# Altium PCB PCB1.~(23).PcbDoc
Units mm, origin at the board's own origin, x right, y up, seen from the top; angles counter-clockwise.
Board outline 32.13 x 39.5 mm, 2 copper layers (Top Layer, Bottom Layer); 17 components, 6 nets, 40 pads, 2 vias.
Unrouted connection lines stored in the file: 16.
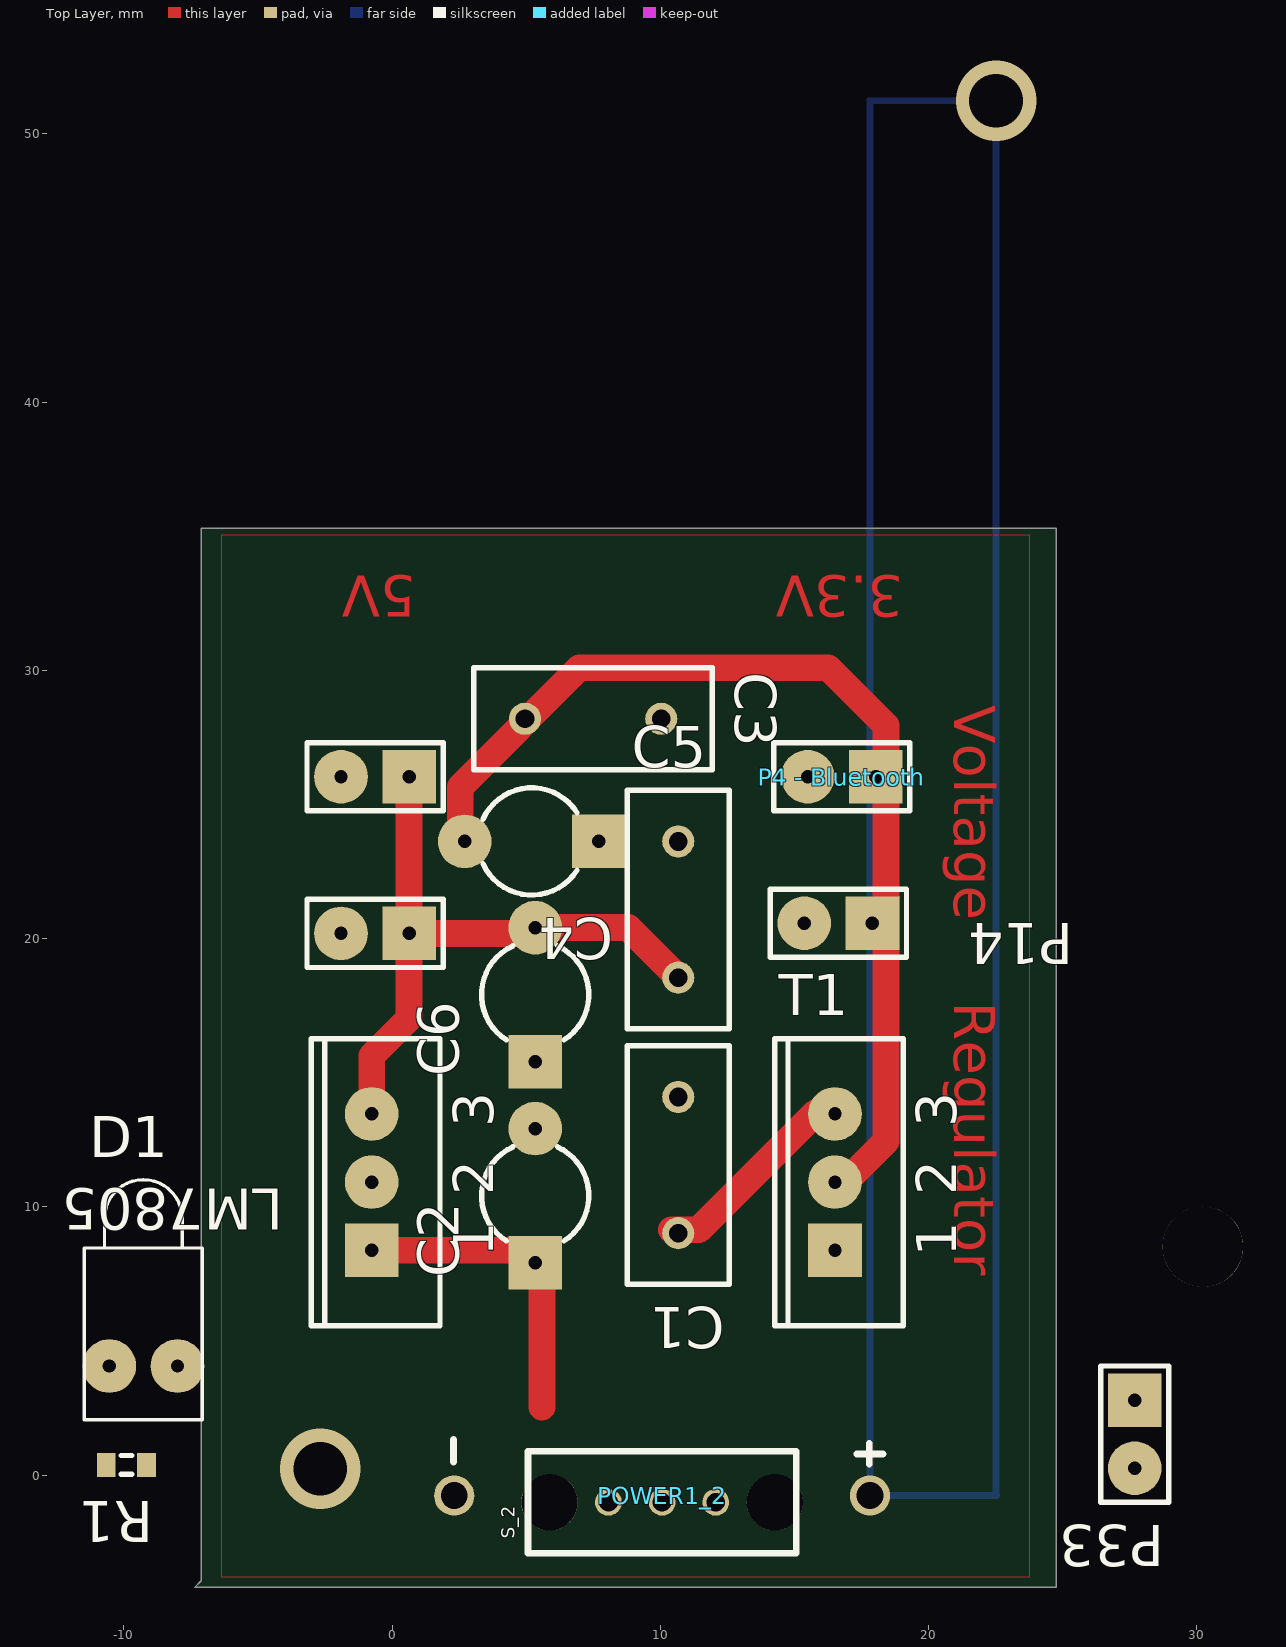
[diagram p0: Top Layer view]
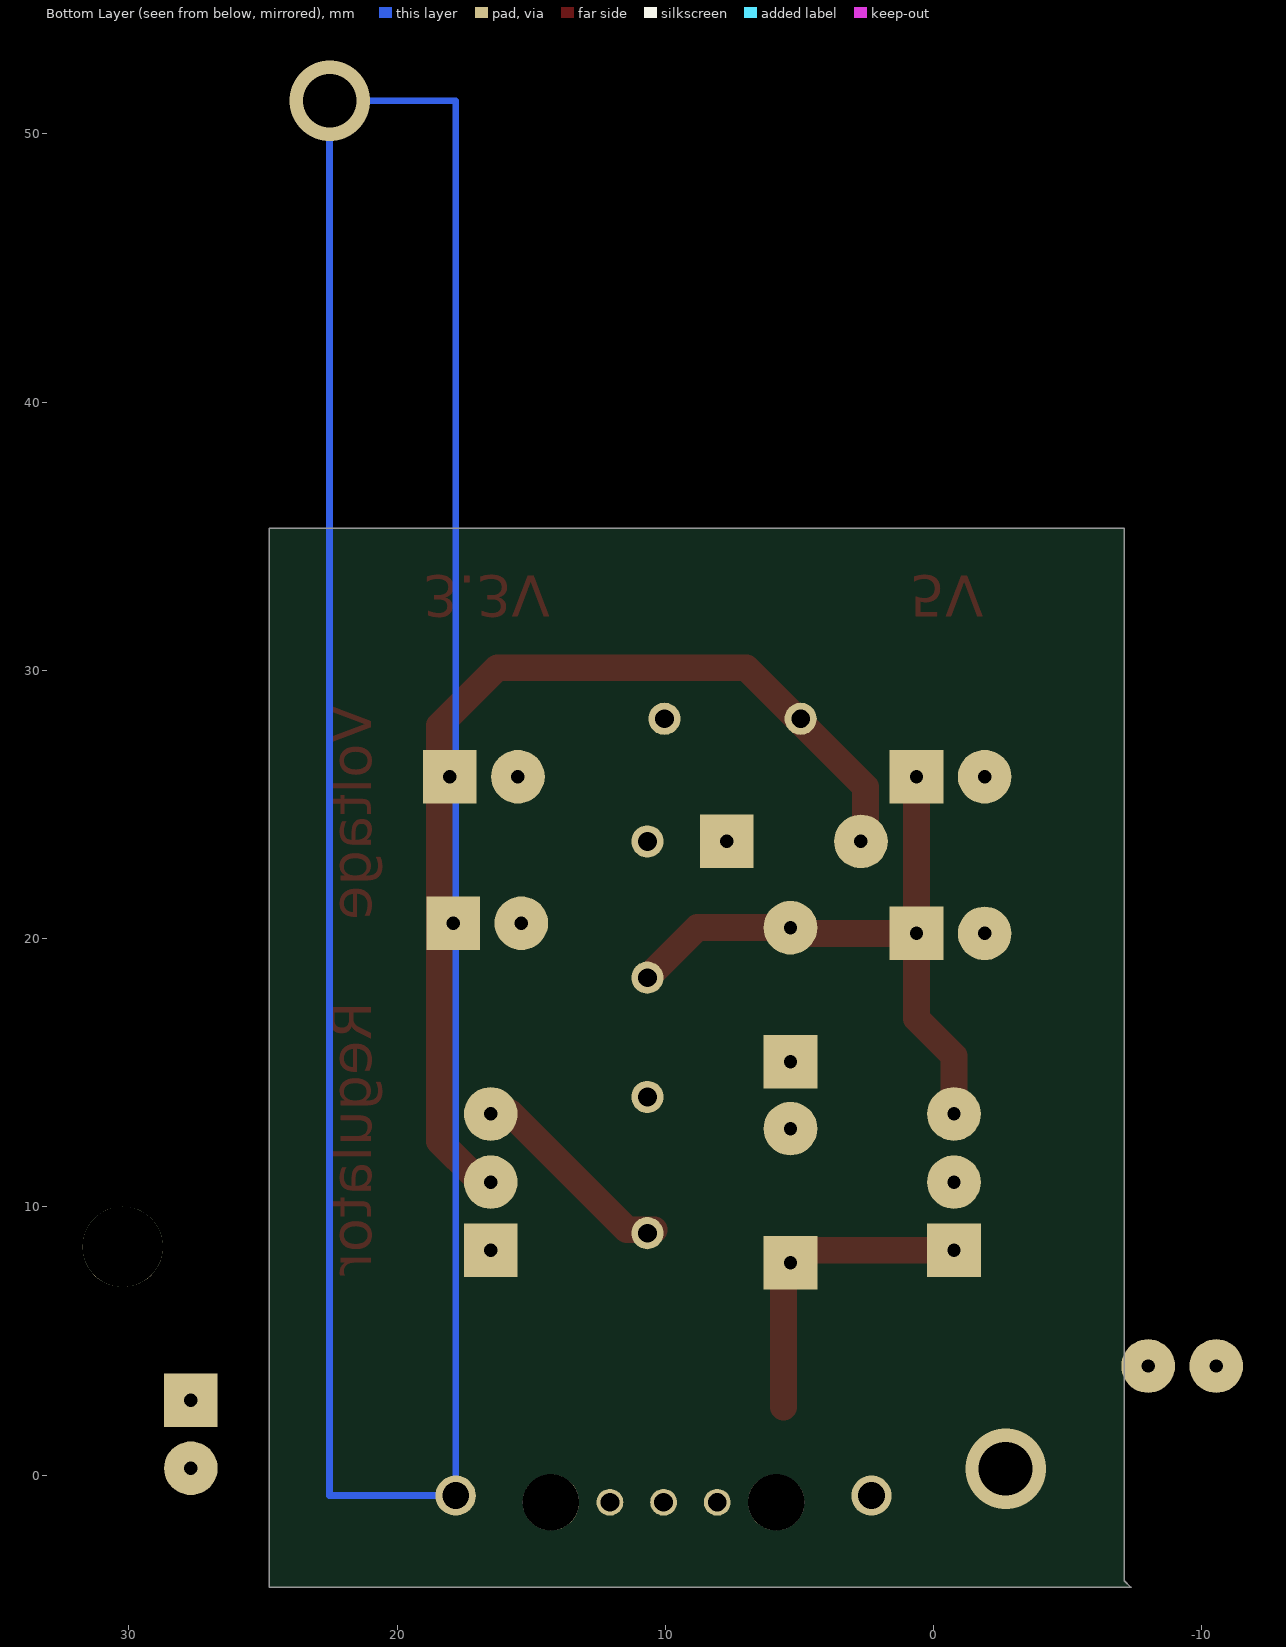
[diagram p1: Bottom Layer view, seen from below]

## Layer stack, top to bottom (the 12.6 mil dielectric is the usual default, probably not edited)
Top Layer: signal copper 0.0356
Dielectric: dielectric 0.32, FR-4, Dk 4.8
Bottom Layer: signal copper 0.0356

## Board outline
24.765,-4.191 24.765,35.306 -7.112,35.306 -7.112,-3.937 -7.366,-4.191

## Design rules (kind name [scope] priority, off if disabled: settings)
Clearance [All] p1: gap=0.5
PlaneClearance [All] p1: clearance=2
PolygonConnect [All] p1: connectstyle=Relief reliefconductorwidth=0.5 reliefentries=4 polygonreliefangle="90 Angle"
RoutingVias [All] p1: holewidth=0.711 width=1.27 viastyle="Through Hole" minholewidth=0.711 minwidth=1.27 maxholewidth=0.711 maxwidth=1.27
SilkscreenOverComponentPads [All] p1: minsilkscreentomaskgap=0.254
SolderMaskExpansion [All] p1: expansion=0.102
Width [All] p1: maxlimit=1 minlimit=0.5 preferedwidth=0.5
26 further rules are at their usual default settings.

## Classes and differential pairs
component class Sheet1: C1 C2 C3 C4 C5 C6 D1 LM7805 P14 P33 R1 T1

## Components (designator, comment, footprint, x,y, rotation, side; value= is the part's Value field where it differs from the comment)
C1 "Cap" RAD-0.2 10.668,11.557 r270 top
C2 "Cap2" CAPR5-4X5 5.334,10.414 r90 top
C3 "Cap" RAD-0.2 7.493,28.194 r0 top
C4 "Cap2" CAPR5-4X5 5.207,23.622 r180 top
C5 "Cap" RAD-0.2 10.668,21.082 r90 top
C6 "Cap2" CAPR5-4X5 5.334,17.907 r90 top
D1 "LED1" LED-1 -9.271,4.064 r90 top
LM7805 "7805" TO-220-AB -0.762,10.922 r90 top locked
"P4 - Bluetooth" "Header 2" HDR1X2 18.034,26.035 r180 top
P10_S_Distancia "Header 2" HDR1X2 0.635,20.193 r180 top
P11_S_Distancia "Header 2" HDR1X2 0.635,26.035 r180 top
P14 "Header 2" HDR1X2 17.907,20.574 r180 top
P33 "Header 2" HDR1X2 27.686,2.794 r270 top
POWER1_2 "POWER_2/5" "POWER Mica" 25.815,-3.266 r90 top (schematic designator POWER1)
R1 "Res3" J1-0603 -9.906,0.381 r180 top
S_2 "SW-SPDT" Switch 10.065,-1.016 r90 top (schematic designator S)
T1 "LM1117" TO-220-AB 16.51,10.922 r90 top locked

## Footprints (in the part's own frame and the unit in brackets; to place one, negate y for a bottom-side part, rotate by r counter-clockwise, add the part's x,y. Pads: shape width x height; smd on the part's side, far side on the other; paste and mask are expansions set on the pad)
CAPR5-4X5 [mm] "Capacitor; 2 Leads"
  rect 2x2 hole 0.5: 1(-2.5,0)
  round 2 hole 0.5: 2(2.5,0)
  silkscreen extent -1.69,-2 1.82,2
HDR1X2 [mm] "Connector; Header; 2 Position"
  rect 2x2 hole 0.5: 1(0,0)
  round 2 hole 0.5: 2(2.54,0)
  silkscreen extent -1.27,-1.27 3.81,1.27
J1-0603 [mm] "Chip Resistor, Body 1.6x0.8mm, IPC High Density"
  rect 0.7x0.9 smd: 1(-0.75,0) 2(0.75,0)
  silkscreen extent -0.2,-0.35 0.2,0.35, body extent -0.85,-0.48 0.85,0.48, height 0.9
LED-1 [mm] "LED; 2 Leads"
  round 2 hole 0.5: 1(0,1.27) 2(0,-1.27)
  silkscreen extent -2,-2.2 6.95,2.2
"POWER Mica" [mm]
  round 1.5 hole 1: 1(2.5,23.5) 2(2.5,8)
  silkscreen extent 3.67,7.51 4.59,23.53
RAD-0.2 [mm] "Radial Cap, Thru-Hole; 2 Leads; 0.2 in Pin Spacing"
  round 1.2 hole 0.7: 1(-2.54,0) 2(2.54,0)
  silkscreen extent -4.44,-1.91 4.44,1.91
Switch [mm]
  round 2.1 hole 2.1: 0(0,4.2) 0(0,-4.2)
  round 1 hole 0.7: 1(0,2) 2(0,0) 3(0,-2)
  silkscreen extent -1.9,-5 1.9,5
TO-220-AB [mm] "TO, Thru-Hole, Vertical, Heatsink Mounted; 3 In-Line Leads; Pitch 2.54 mm"
  rect 2x2 hole 0.5: 1(-2.54,0)
  round 2 hole 0.5: 2(0,0) 3(2.54,0)
  silkscreen extent -5.35,-2.55 5.35,2.25

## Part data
C1 C2 C3 C4 C5 C6: "Capacitor"
D1: "Typical RED GaAs LED"
LM7805 T1: library part 2N3906, "PNP General Purpose Amplifier"
"P4 - Bluetooth" P10_S_Distancia P11_S_Distancia P14 P33: "Header, 2-Pin"
R1: "Resistor"
S_2: "SPDT Subminiature Toggle Switch, Right Angle Mounting, Vertical Actuation"

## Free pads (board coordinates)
  round 3 hole 3: 0(30.226,8.509)

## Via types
v1: diameter 3, hole 2, Top Layer to Bottom Layer, 2 vias

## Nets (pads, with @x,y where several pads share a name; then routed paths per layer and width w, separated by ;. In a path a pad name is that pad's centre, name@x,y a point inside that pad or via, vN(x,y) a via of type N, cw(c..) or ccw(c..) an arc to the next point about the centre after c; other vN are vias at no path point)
GND: "P4 - Bluetooth.2" C1.1 C2.2 C3.2 C4.1 C5.2 C6.1 LM7805.2 P10_S_Distancia.2 P11_S_Distancia.2 P14.2 P33.1 R1.1 T1.1
NetC1_2: C1.2 C2.1 D1.1 LM7805.1 T1.3 | length 18.9
  Top Layer w1: LM7805.1 4.659,8.382 5.588,7.453 5.588,5.08 5.588,2.54 ; C1.2@10.414,9.144 11.43,9.144 T1.3@15.811,13.525
NetC3_1: "P4 - Bluetooth.1" C3.1 C4.2 P14.1 T1.2 | length 38.7
  Top Layer w1: C4.2@2.54,23.749 2.54,25.654 6.985,30.099 16.256,30.099 18.415,27.94 18.415,12.446 17.081,11.112 T1.2@16.319,11.112
NetC5_1: C5.1 C6.2 LM7805.3 P10_S_Distancia.1 P11_S_Distancia.1 | length 24.2
  Top Layer w1: LM7805.3 -0.762,15.621 0.635,17.018 P10_S_Distancia.1 ; P10_S_Distancia.1@0.508,20.193 P10_S_Distancia.1 ; P11_S_Distancia.1 P10_S_Distancia.1 ; C5.1 8.803,20.407 C6.2 5.12,20.193 P10_S_Distancia.1
NetD1_2: D1.2 R1.2
NetP25_3: P33.2
pads on no net: POWER1_2.1 POWER1_2.2 S_2.0 S_2.1 S_2.2 S_2.3
copper on no net: | length 114.1
  Top Layer w0.2: v1(-2.685,0.234) v1@-2.685,0.954
  Bottom Layer w0.254: 17.815,51.224 17.815,-0.766 22.527,-0.766 ; 17.815,51.234 v1(22.515,51.234) 22.515,-0.766

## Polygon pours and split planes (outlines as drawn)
GND on Top Layer "Top Layer-No Net" (solid, shelved, pour order 2): 23.749,-3.81 -6.35,-3.81 -6.35,35.052 23.749,35.052

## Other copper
Top Layer:
  text "5V" at 0.889,33.528 h1.52 r180
  text "3.3V" at 19.05,33.528 h1.52 r180
  text "Voltage" at 20.955,28.702 h1.52 r270
  text "Regulator" at 20.955,17.653 h1.52 r270

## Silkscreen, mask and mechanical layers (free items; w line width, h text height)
Mechanical 1:
  lines w0.254: -5.773,8.41 -5.27,6.884 ; -5.656,44.224 -5.143,45.746 ; -5.524,6.885 -5.016,6.883 ; -5.397,45.747 -4.889,45.745 ; -5.233,18.291 -5.27,6.884 ; -5.181,34.339 -5.143,45.746 ; -4.757,8.406 -5.27,6.884 ; -4.64,44.22 -5.143,45.746 ; -0.129,46.736 -0.125,46.228 ; 1.393,47.003 -0.127,46.482 ; 1.401,45.987 -0.127,46.482 ; 6.962,46.542 -0.127,46.482 ; 23.01,46.676 30.099,46.736 ; 28.571,47.231 30.099,46.736 ; 28.579,46.215 30.099,46.736 ; 30.097,46.99 30.101,46.482
  lines w1: -5.185,-3.192 -5.185,21.573
  text "30.227 (mm)" at 7.224,45.63 h1.52 r0.48
  text "38.862 (mm)" at -4.318,18.542 h1.52 r89.81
